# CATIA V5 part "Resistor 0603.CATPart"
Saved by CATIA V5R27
Part number: Resistor 0603
Definition: Resistor 0603
Nomenclature: Resistor 0603 v2
Source: Unknown
Bounding box of the stored display mesh (mm): x 0 to 1.7, y 0.05 to 0.6, z 0 to 0.9
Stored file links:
  E:\university\my-thesis\My Thesis Publication\Final-Updata\CAD\Resistor 0603.CATPart
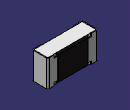
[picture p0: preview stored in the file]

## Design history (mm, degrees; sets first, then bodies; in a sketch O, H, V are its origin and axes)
Body1 "Body1" (main body)
  Solid1: solid without history
Body2 "Body2"
  Solid2: solid without history
Body3 "Body3"
  Solid3: solid without history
